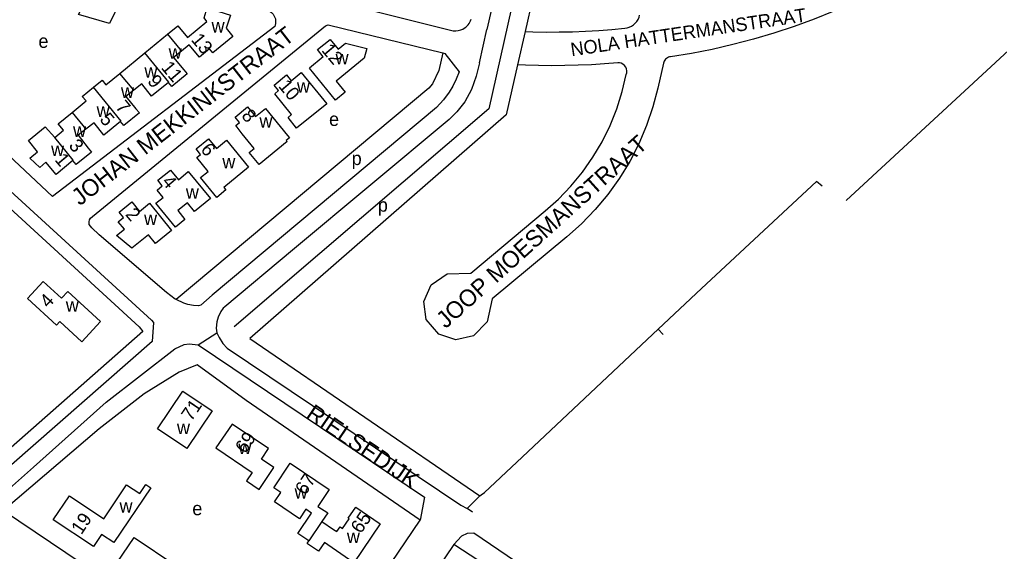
# Model space of a CAD drawing. Extents: x 162804 to 165059, y 381530 to 382901.
# Drawn here: x 164009 to 164299.3, y 381888 to 382045.7 of the extents above; entities that cross this region are included whole.
import ezdxf

# ---------------------------------------------------------------- set-up
doc = ezdxf.new("R2010")
doc.units = 0
for name, color, linetype in [('BLT_Basislijn', 7, 'Continuous'), ('BLT_Bebouwing', 7, 'Continuous'), ('BLT_Centroide', 7, 'Continuous'), ('BLT_Huisnummer', 7, 'Continuous'), ('BLT_Onderverdeling_panden', 7, 'Continuous'), ('BLT_Plantopo', 7, 'Continuous'), ('BLT_Straatnaam', 7, 'Continuous'), ('BLT_Straatnaam_verkleind', 7, 'Continuous'), ('BLT_Vlakafsluiter', 7, 'Continuous')]:
    doc.layers.add(name, color=color, linetype=linetype)

msp = doc.modelspace()

# ---------------------------------------------------------------- linework, layer by layer
at = {"layer": 'BLT_Basislijn'}
for p, q in [((164189.14, 382176.35), (164158.8, 382042.14)), ((164253.93, 381992), (164359.35, 382089.62)), ((164084.65, 382043.67), (164018.83, 381993.23)), ((164030.62, 381987.32), (164098.6, 382042.91)), ((164098.6, 382042.91), (164099.7, 382043.8)), ((164099.7, 382043.8), (164100.46, 382044.08)), ((164100.46, 382044.08), (164134.46, 382035.8)), ((164145.26, 382032.88), (164147.51, 382042.71)), ((164158.8, 382042.14), (164156.55, 382032.22)), ((164134.46, 382035.8), (164135.07, 382035.65)), ((164135.07, 382035.65), (164139.26, 382030.15)), ((164139.26, 382030.15), (164138.37, 382027.98)), ((164138.37, 382027.98), (164137.41, 382025.95)), ((164137.41, 382025.95), (164136.35, 382024.16)), ((164134.6, 382021.86), (164132.53, 382019.65)), ((164136.35, 382024.16), (164134.6, 382021.86)), ((163989.12, 382020.94), (164018.83, 381993.23)), ((164132.53, 382019.65), (164066.09, 381964.03)), ((164245.09, 381997.63), (164211.05, 381965.96)), ((164246.84, 381996.27), (164245.09, 381997.63)), ((164029.72, 381986.28), (164030.07, 381986.77)), ((164030.07, 381986.77), (164030.62, 381987.32)), ((164029.62, 381985.68), (164029.72, 381986.28)), ((164029.62, 381984.93), (164029.62, 381985.68)), ((164030.41, 381983.93), (164029.62, 381984.93)), ((164032.66, 381981.9), (164030.41, 381983.93)), ((164052.6, 381964.76), (164032.66, 381981.9)), ((164055.17, 381962.82), (164052.6, 381964.76)), ((164066.09, 381964.03), (164062.74, 381961.05)), ((164211.05, 381965.96), (164198.23, 381953.92)), ((164055.41, 381962.71), (164055.17, 381962.82)), ((164057.71, 381961.64), (164055.41, 381962.71)), ((164058.85, 381961.26), (164057.71, 381961.64)), ((164060.56, 381960.89), (164058.85, 381961.26)), ((164062.03, 381960.8), (164060.56, 381960.89)), ((164062.74, 381961.05), (164062.03, 381960.8)), ((164198.23, 381953.92), (164156.32, 381914.53)), ((164198.23, 381953.92), (164199.75, 381952.35)), ((164001.14, 381902.31), (164013.17, 381912.96)), ((164141.62, 381900.77), (164145.39, 381904.49)), ((164004.28, 381900.2), (164087.97, 381843.76)), ((164092.13, 381844.57), (164127.67, 381897.27))]:
    msp.add_line(p, q, dxfattribs=at)
for points in [[(164183.14, 382177.78), (164181.33, 382175.96), (164179.73, 382174.07), (164177.98, 382171.37), (164176.81, 382168.98), (164175.86, 382166.44), (164175.29, 382164.13), (164147.51, 382042.71)], [(164182.02, 382170.78), (164148.04, 382019.21), (164072.57, 381954.59)], [(164105.5, 382050.37), (164137.05, 382042.48), (164137.53, 382042.38), (164138.28, 382042.35), (164138.99, 382042.41), (164139.77, 382042.6), (164140.34, 382042.84), (164140.77, 382043.08), (164141.28, 382043.46), (164141.63, 382043.78), (164141.96, 382044.13), (164142.26, 382044.55), (164142.57, 382045.1), (164142.67, 382045.29), (164142.82, 382045.75)], [(164082.29, 382048.47), (164083.07, 382048.17), (164083.68, 382047.76), (164084.18, 382047.32), (164084.49, 382046.73), (164084.87, 382045.9), (164084.87, 382045.27), (164084.87, 382044.52), (164084.65, 382043.67)], [(163942.85, 382045.24), (163943.88, 382045.91), (163944.68, 382046.18), (163945.43, 382046.3), (163946.28, 382046.34), (163947.14, 382046.2), (163947.91, 382045.97), (163948.94, 382045.37), (163974.77, 382023.71), (164048.11, 381956.56), (164048.67, 381955.87), (164048.35, 381950.3), (163846.25, 381773.14), (163842.47, 381770.18), (163838.71, 381770.12), (163836.54, 381770.96)], [(163942.85, 382045.24), (163967.78, 382024.92), (164044.46, 381954.63), (164045.58, 381953.26), (163979.85, 381895.4), (163836.54, 381770.96)], [(164134.46, 382035.8), (164133.26, 382030.59), (164131.37, 382026.58), (164130.27, 382025.34), (164055.41, 381962.71)], [(164156.55, 382032.22), (164153.21, 382017.43), (164077.26, 381951.17), (164145.39, 381904.49)], [(164144.72, 382030.5), (164144.31, 382028.86), (164142.88, 382024.98), (164140.9, 382021.33), (164138.54, 382018.36), (164136.31, 382016.1), (164089.87, 381977.37)], [(164145.26, 382032.88), (164144.72, 382030.5)], [(164089.87, 381977.37), (164069.82, 381960.56), (164069.36, 381960.18), (164068.64, 381959.1), (164067.92, 381957.51), (164067.46, 381956.07), (164067.25, 381954.17), (164067.51, 381952.83)], [(164067.51, 381952.83), (164068.12, 381951.39), (164069.25, 381949.7), (164070.49, 381948.32), (164139.77, 381901.78), (164141.62, 381900.77)], [(164013.17, 381912.96), (164034.71, 381932.25), (164055.04, 381948.1), (164057.84, 381949.36), (164059.27, 381949.52), (164061.92, 381949.28)], [(164061.92, 381949.28), (164129.04, 381904.07), (164127.67, 381897.27)], [(164127.67, 381897.27), (164076.18, 381932.74), (164061.65, 381943.36), (164056.35, 381941.19), (164045.96, 381934.74), (164032.59, 381924.37), (164004.28, 381900.2)], [(164145.39, 381904.49), (164145.74, 381904.84), (164146.77, 381905.51), (164156.32, 381914.53)], [(164143.25, 381899.66), (164141.62, 381900.77)], [(164160.87, 381881.69), (164143.57, 381893.41), (164141.61, 381893.3), (164139.98, 381892.53), (164137.69, 381890.12)], [(164172.17, 381867.54), (164137.69, 381890.12), (164073.54, 381794.99)]]:
    msp.add_lwpolyline(points, dxfattribs=at)
at = {"layer": 'BLT_Bebouwing'}
for p, q in [((164052.91, 382041.31), (164055.94, 382043.79)), ((164055.94, 382043.79), (164058.75, 382040.36)), ((164046.19, 382035.81), (164052.91, 382041.31)), ((164101.01, 382039.78), (164103.4, 382036.86)), ((164056.99, 382036.33), (164054.68, 382034.42)), ((164059.3, 382038.23), (164056.99, 382036.33)), ((164066.25, 382035.8), (164065.26, 382036.99)), ((164103.4, 382036.86), (164105.6, 382038.66)), ((164105.6, 382038.66), (164111.87, 382037.14)), ((164111.87, 382037.14), (164111.15, 382034.19)), ((164038.76, 382029.74), (164046.19, 382035.81)), ((164099.02, 382034.64), (164094.89, 382031.25)), ((164102.59, 382021.8), (164094.89, 382031.25)), ((164088.13, 382029.26), (164089.53, 382027.55)), ((164089.53, 382027.55), (164092.48, 382029.97)), ((164042.88, 382024.72), (164040.55, 382022.83)), ((164045.21, 382026.61), (164042.88, 382024.72)), ((164089.61, 382017.5), (164084.65, 382023.71)), ((164072.89, 382016.74), (164076.59, 382019.79)), ((164076.59, 382019.79), (164078.93, 382016.93)), ((164078.93, 382016.93), (164081.89, 382019.35)), ((164081.89, 382019.35), (164088.46, 382011.34)), ((164020.48, 382014.78), (164024.6, 382018.16)), ((164019.47, 382010.72), (164022.06, 382012.85)), ((164022.06, 382012.85), (164020.48, 382014.78)), ((164028.66, 382013.18), (164026.42, 382011.45)), ((164031.15, 382015.1), (164028.66, 382013.18)), ((164015.01, 382001.85), (164012.04, 382004.6)), ((164015.01, 382001.85), (164016.84, 382003.39)), ((164038.54, 381988.61), (164042.26, 381991.65)), ((164042.26, 381991.65), (164044.59, 381988.8)), ((164044.59, 381988.8), (164047.55, 381991.21)), ((164047.55, 381991.21), (164054.09, 381983.18)), ((164047.21, 381981.91), (164042.27, 381977.89)), ((164049.33, 381979.3), (164047.21, 381981.91)), ((164054.09, 381983.18), (164049.33, 381979.3)), ((164037.93, 381884.74), (164042.96, 381892.2)), ((164042.96, 381892.2), (164055.31, 381883.87))]:
    msp.add_line(p, q, dxfattribs=at)
for points in [[(164040.36, 382054.21), (164035.72, 382044.54), (164026.54, 382047.19), (164027.27, 382048.66)], [(164058.75, 382040.36), (164064.56, 382045.11), (164063.69, 382046.17), (164064.63, 382049.13)], [(164064.63, 382049.13), (164071.48, 382046.94), (164070.25, 382043.08), (164072.21, 382040.69), (164066.25, 382035.8)], [(164099.02, 382034.64), (164097.3, 382036.76), (164101.01, 382039.78)], [(164065.26, 382036.99), (164062.32, 382034.58), (164059.3, 382038.23)], [(164054.68, 382034.42), (164057.67, 382030.8), (164058.65, 382029.6), (164054.13, 382025.87), (164053.15, 382027.06)], [(164111.15, 382034.19), (164102.85, 382027.42), (164105.5, 382024.17), (164102.59, 382021.8)], [(164030.9, 382025.6), (164033.51, 382027.73), (164034.63, 382026.36), (164038.76, 382029.74)], [(164084.65, 382023.71), (164085.77, 382024.63), (164084.46, 382026.22), (164088.13, 382029.26)], [(164092.48, 382029.97), (164100.02, 382020.74), (164091.12, 382013.52), (164088.6, 382016.69), (164089.61, 382017.5)], [(164024.6, 382018.16), (164028.74, 382021.54), (164027.62, 382022.91), (164030.9, 382025.6)], [(164053.15, 382027.06), (164048.16, 382022.97), (164045.21, 382026.61)], [(164040.55, 382022.83), (164043.51, 382019.18), (164044.55, 382018.03), (164039.95, 382014.27), (164038.98, 382015.49)], [(164078.51, 382007.5), (164075.03, 382011.76), (164073.49, 382013.76), (164073.09, 382014.24), (164074.2, 382015.15), (164072.89, 382016.74)], [(164012.04, 382004.6), (164014.37, 382006.52), (164011.73, 382009.85), (164016.61, 382013.87), (164019.47, 382010.72)], [(164038.98, 382015.49), (164034.01, 382011.39), (164031.15, 382015.1)], [(164026.42, 382011.45), (164029.4, 382007.59), (164030.33, 382006.39), (164025.81, 382002.67), (164024.8, 382003.91)], [(164067.46, 381992.94), (164062.64, 381998.83), (164064.87, 382000.66), (164061.54, 382004.82), (164062.65, 382005.72), (164061.35, 382007.32), (164065.04, 382010.34), (164067.38, 382007.47), (164070.34, 382009.89), (164076.88, 382001.88), (164069.57, 381995.91), (164070.17, 381995.16), (164067.46, 381992.94)], [(164088.46, 382011.34), (164089.01, 382010.67), (164088.02, 382009.87), (164088.31, 382009.51), (164079.99, 382002.7)], [(164079.99, 382002.7), (164077.05, 382006.3), (164078.51, 382007.5)], [(164024.8, 382003.91), (164019.86, 381999.78), (164016.84, 382003.39)], [(164049.77, 381995.14), (164051.33, 381996.43), (164050.02, 381998.03), (164053.73, 382001.08), (164056.08, 381998.22), (164059.03, 382000.64), (164065.59, 381992.65), (164060.87, 381988.77), (164058.74, 381991.37), (164055.89, 381989.04), (164058.02, 381986.44), (164055.2, 381984.13)], [(164055.2, 381984.13), (164049.39, 381991.23), (164051.54, 381992.98), (164049.77, 381995.14)], [(164042.27, 381977.89), (164037.8, 381981.63), (164040.09, 381983.5), (164038.28, 381985.72), (164039.86, 381987.02), (164038.54, 381988.61)], [(164021.5, 381963.06), (164023.37, 381965.09), (164033.06, 381956.22), (164027.51, 381950.16), (164020.98, 381956.13), (164019.99, 381955.05), (164011.37, 381962.95), (164016.05, 381968.06), (164021.5, 381963.06)], [(164094.72, 381891.12), (164091.51, 381893.29), (164095.57, 381899.33), (164093.81, 381900.51), (164091.93, 381897.71), (164084.52, 381902.74), (164086.41, 381905.53), (164084.35, 381906.92), (164089.24, 381914.14), (164100.78, 381906.34), (164097.42, 381901.38), (164100.32, 381899.44), (164098.6, 381896.89)], [(164098.6, 381896.89), (164102.05, 381894.56), (164103.02, 381893.9), (164103.97, 381895.29), (164104.68, 381894.81), (164106.65, 381897.72), (164106.42, 381897.88), (164108.64, 381901.15), (164115.9, 381896.21), (164108.05, 381884.66), (164100.36, 381890), (164099.39, 381890.68), (164097.62, 381888.06), (164094.3, 381890.32), (164094.21, 381890.38), (164094.72, 381891.12)]]:
    msp.add_lwpolyline(points, dxfattribs=at)
for points in [[(164057.42, 381935.55), (164066.13, 381929.68), (164058.55, 381918.51), (164049.9, 381924.35)], [(164071.97, 381925.76), (164067.22, 381918.72), (164077.97, 381911.46), (164076.28, 381908.96), (164080.02, 381906.39), (164084.39, 381912.9), (164080.67, 381915.39), (164082.75, 381918.5)], [(164023.78, 381904.48), (164033.98, 381897.66), (164040.73, 381907.77), (164044.63, 381905.16), (164046.45, 381907.88), (164047.91, 381906.9), (164037, 381890.63), (164033.35, 381893.08), (164030.9, 381889.44), (164019.03, 381897.37)]]:
    msp.add_lwpolyline(points, close=True, dxfattribs=at)
at = {"layer": 'BLT_Onderverdeling_panden'}
for p, q in [((164052.91, 382041.31), (164056.99, 382036.33)), ((164042.88, 382024.72), (164038.76, 382029.74)), ((164024.6, 382018.16), (164028.66, 382013.18))]:
    msp.add_line(p, q, dxfattribs=at)
for points in [[(164053.15, 382027.06), (164053.27, 382027.15), (164046.19, 382035.81)], [(164038.98, 382015.49), (164039.1, 382015.58), (164030.9, 382025.6)], [(164024.8, 382003.91), (164024.92, 382004.02), (164019.47, 382010.72)], [(164098.6, 381896.89), (164094.72, 381891.12)]]:
    msp.add_lwpolyline(points, dxfattribs=at)
at = {"layer": 'BLT_Plantopo'}
for p, q in [((164199.79, 382032.75), (164198.14, 382025.39)), ((164142.68, 381970.53), (164164.79, 381988.96)), ((164171.19, 381981.28), (164149.09, 381962.85))]:
    msp.add_line(p, q, dxfattribs=at)
for points in [[(164255.95, 382050.78), (164250.23, 382048.21), (164244.41, 382045.83), (164238.51, 382043.64), (164232.53, 382041.64), (164226.49, 382039.84), (164220.39, 382038.25), (164214.25, 382036.85), (164208.08, 382035.66), (164201.88, 382034.68)], [(164188.37, 382043.1), (164189.02, 382043.21), (164189.67, 382043.41), (164190.31, 382043.71), (164190.9, 382044.1), (164191.44, 382044.58), (164191.9, 382045.12), (164192.27, 382045.72), (164192.55, 382046.34), (164192.74, 382046.98)], [(164158.8, 382042.14), (164161.1, 382042.06), (164165, 382041.99), (164168.9, 382042), (164172.81, 382042.07), (164176.71, 382042.22), (164180.6, 382042.44), (164184.49, 382042.73), (164188.37, 382043.1)], [(164201.88, 382034.68), (164201.57, 382034.62), (164201.25, 382034.51), (164200.95, 382034.35), (164200.67, 382034.16), (164200.41, 382033.92), (164200.2, 382033.66), (164200.02, 382033.37), (164199.88, 382033.06), (164199.79, 382032.75)], [(164186.23, 382032.85), (164182.33, 382032.54), (164178.43, 382032.3), (164174.53, 382032.12), (164170.62, 382032.02), (164166.71, 382031.98), (164162.8, 382032.02), (164158.89, 382032.12), (164156.55, 382032.22)], [(164188.77, 382029.44), (164188.91, 382029.92), (164188.94, 382030.46), (164188.85, 382031.04), (164188.62, 382031.6), (164188.25, 382032.09), (164187.78, 382032.47), (164187.25, 382032.72), (164186.72, 382032.84), (164186.23, 382032.85)], [(164164.79, 381988.96), (164168.7, 381992.48), (164172.37, 381996.31), (164175.76, 382000.45), (164178.85, 382004.85), (164181.59, 382009.48), (164183.97, 382014.3), (164185.96, 382019.26), (164187.57, 382024.32), (164188.77, 382029.44)], [(164198.14, 382025.39), (164196.67, 382019.8), (164194.79, 382014.29), (164192.49, 382008.89), (164189.8, 382003.65), (164186.72, 381998.62), (164183.29, 381993.83), (164179.54, 381989.33), (164175.49, 381985.13), (164171.19, 381981.28)], [(164149.09, 381962.85), (164147.57, 381956.05), (164143.51, 381951.95), (164138.31, 381950.75), (164133.24, 381952.39), (164129.54, 381956.82), (164128.84, 381962.11), (164130.95, 381967.01), (164135.72, 381970.27), (164142.68, 381970.53)]]:
    msp.add_lwpolyline(points, dxfattribs=at)
at = {"layer": 'BLT_Vlakafsluiter'}
msp.add_line((164061.92, 381949.28), (164067.51, 381952.83), dxfattribs=at)

# ---------------------------------------------------------------- texts
at = {"layer": 'BLT_Centroide'}
for s, p in [('w', (164065.91, 382041.84)), ('e', (164014.63, 382037.29)), ('w', (164053.2, 382034.08)), ('w', (164102.65, 382032.41)), ('w', (164046.02, 382028.44)), ('w', (164039.08, 382022.47)), ('w', (164091.2, 382024.03)), ('w', (164031.87, 382016.84)), ('w', (164080.09, 382013.62)), ('e', (164100.72, 382014.14)), ('w', (164024.89, 382010.91)), ('w', (164018.37, 382005.25)), ('w', (164069.11, 382001.58)), ('p', (164107.42, 382002.55)), ('w', (164058.3, 381992.59)), ('p', (164115.17, 381988.73)), ('w', (164045.92, 381984.78)), ('w', (164022.73, 381959.09)), ('w', (164055.66, 381922.79)), ('w', (164073.86, 381916.86)), ('w', (164090.5, 381903.7)), ('w', (164038.64, 381899.53)), ('e', (164060.21, 381898.75)), ('w', (164106, 381890.52))]:
    msp.add_text(s, height=4, dxfattribs=at).set_placement(p)
at = {"layer": 'BLT_Huisnummer'}
for s, rotation, p in [('13', 309.9871, (164059.66, 382039.6)), ('12', 310.1258, (164098.3, 382036.5)), ('11', 310.0322, (164050.8, 382031.32)), ('9', 309.9871, (164046.72, 382027.27)), ('10', 310.1258, (164085.5, 382025.87)), ('7', 310.0401, (164037.26, 382019.65)), ('8', 310.1258, (164074.56, 382017.05)), ('5', 309.9871, (164032.55, 382015.98)), ('3', 310.0361, (164023.4, 382008.2)), ('6', 310.1258, (164062.48, 382007.04)), ('1', 309.9871, (164019.26, 382004.04)), ('4', 310.1258, (164050.98, 381997.47)), ('2', 310.1258, (164040.2, 381987.82)), ('4', 47.5208, (164017.55, 381959.95)), ('71', 56.0033, (164059.95, 381926.41)), ('69', 56.0033, (164075.92, 381916.78)), ('67', 56.0033, (164093.67, 381904.47)), ('65', 56.0033, (164110.15, 381893.07)), ('19', 56.0039, (164027.34, 381892.78))]:
    msp.add_text(s, height=4, rotation=rotation, dxfattribs=at).set_placement(p)
at = {"layer": 'BLT_Straatnaam'}
for s, rotation, p in [('JOHAN MEKKINKSTRAAT', 37.8526, (164026.89, 381990.3)), ('JOOP MOESMANSTRAAT', 42.0267, (164135.27, 381953.89)), ('RIELSEDIJK', 325.8608, (164093.52, 381927.8))]:
    msp.add_text(s, height=5, rotation=rotation, dxfattribs=at).set_placement(p)
at = {"layer": 'BLT_Straatnaam_verkleind'}
msp.add_text('NOLA HATTERMANSTRAAT', height=4, rotation=8.4656, dxfattribs=at).set_placement((164172.59, 382034.77))

doc.saveas('drawing.dxf')
